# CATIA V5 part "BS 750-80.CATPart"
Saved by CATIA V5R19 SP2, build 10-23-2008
Part number: BS 750-80
Bounding box of the stored display mesh (mm): x -22.494 to 22.494, y -22.494 to 22.494, z 0 to 192
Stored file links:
  C:\Users\Bora\Desktop\3D Katı model\BS serisi\BS 750\BS 750-80.CATPart
  C:\Program Files\Dassault Systemes\B19\intel_a\reffiles\standard\MetricThickPitch.txt
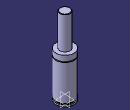
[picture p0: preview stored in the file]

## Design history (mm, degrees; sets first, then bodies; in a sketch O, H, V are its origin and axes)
Body1 (main body)
  Sketch1 on yz-plane, origin (0, 0, 0), H (0, 1, 0), V (0, 0, 1)
    point P3 (12.5, 191)
    point P5 (12.5, 191)
    point P7 (22.5, 97.5)
    point P8 (22.5, 95.5)
    point P12 (22.5, 95.5)
    point P13 (22.5, 97.5)
    line L1 (22.5, 0) -> (22.5, 4)
    line L2 (12.5, 191) -> (12.5, 111)
    arc A1 centre (11.5, 191) radius 1 from (12.5, 191) to (11.5, 192) ccw
    arc A2 centre (22.5, 96.5) radius 1 from (22.5, 97.5) to (22.5, 95.5) ccw
    line L3 (20, 7.5) -> (20, 4)
    line L4 (22.5, 7.5) -> (22.5, 95.5)
    line L5 (22.5, 97.5) -> (22.5, 111)
    line L6 (11.5, 192) -> (0, 192)
    point P15 (0, 192)
    line L7 (12.5, 111) -> (22.5, 111)
    line L8 (0, 0) -> (22.5, 0)
    line L9 (20, 7.5) -> (22.5, 7.5)
    line L10 (20, 4) -> (22.5, 4)
    coincidence: P15 V, P3 P5, P7 P13, P8 P12
    tangency: L6 A1
    horizontal: L7 H, L8 H, L9 H, L10 H
  Shaft1: profile Sketch1, axis Sketch1.V, angle 360
  Sketch2 on face of Shaft1 from Sketch1.L8, origin (0, 0, 0), H (1, 0, 0), V (0, -1, 0)
    point P1 (10, 0)
    distance P1 V = 10
  Hole1: placed by Sketch2, at (10, 0, 0) direction (0, 0, 1), diameter 6.647, depth 4, threaded "M8", thread diameter 8, thread depth 4, pitch 1.25
  CircPattern1: of Hole1, instances 2, angular step 180, axis from xy-plane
